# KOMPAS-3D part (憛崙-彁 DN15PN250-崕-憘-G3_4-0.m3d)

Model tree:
1. Объединить компоненты:1  (labels: СЕНС-ПР DN15PN250-НО-G3/4-0)
2. Эскиз:1
3. Операция выдавливания:1
     Расстояние 1 = 14
4. Фаска:1
     Угол = 45; Длина 1 = 2; Длина 2 = 2

Referenced files in D:\Савин\!СЕНСОР\3D для заказчика\!Новый перечень\СЕНС-ПР\6. СЕНС-ПР-PN250-НО\DN15\: СЕНС-ПР DN15PN250-НО-G3_4-0.a3d
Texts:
  СЕНС-ПР DN15PN250-НО-СВ-G3/4-0
  ООО НПП Сенсор
  СЕНС-ПР DN15PN250-НО-G3/4-0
